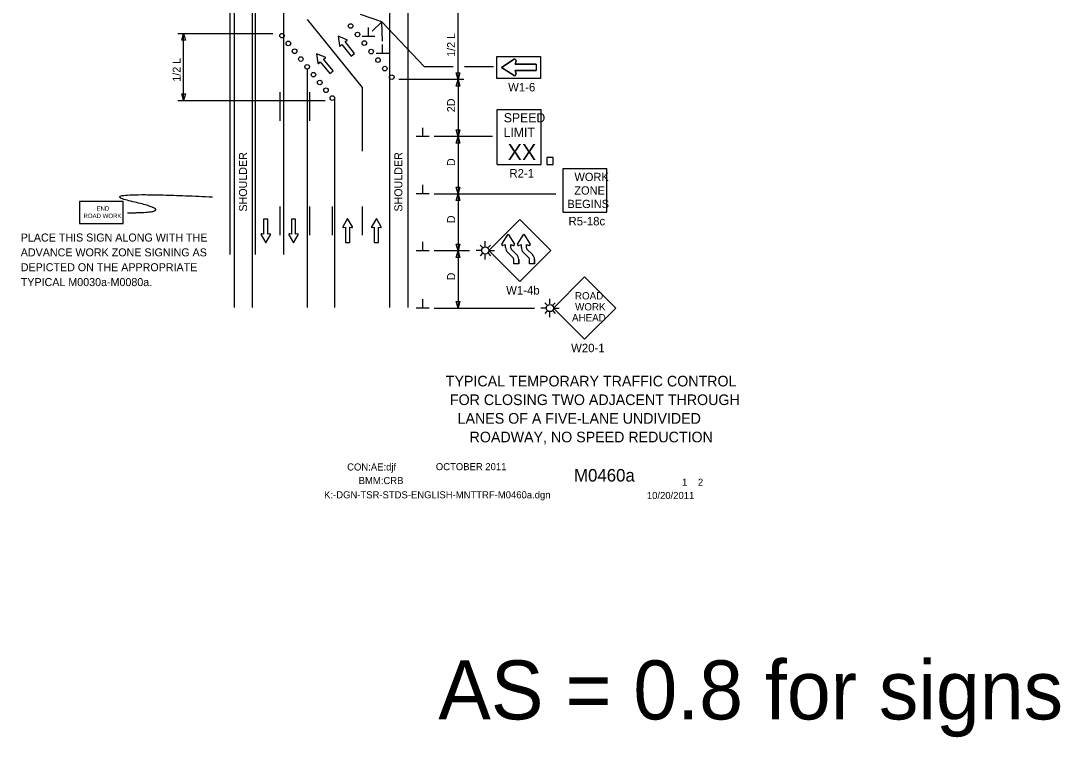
# Model space of a CAD drawing. Extents: x 16752 to 18475, y 7011 to 8262.
# Drawn here: x 16805 to 17715, y 7011 to 7638 of the extents above; entities that cross this region are included whole.
import ezdxf

# ---------------------------------------------------------------- set-up
doc = ezdxf.new("R2010")
doc.units = 0
for name, color, linetype in [('ALI_LEGAL_EX', 7, 'Continuous'), ('BORDER', 7, 'Continuous'), ('BORDER_SIGNAL_WO', 7, 'Continuous'), ('MT_SCRATCH_LEVEL_E', 7, 'Continuous'), ('PAVT_EDGE_EX', 7, 'Continuous'), ('TRAFFIC_SIGNS_PR', 7, 'Continuous'), ('TYPICAL_TEXT_DIMEN_PR', 7, 'Continuous')]:
    doc.layers.add(name, color=color, linetype=linetype)

msp = doc.modelspace()

# ---------------------------------------------------------------- linework, layer by layer
at = {"layer": 'ALI_LEGAL_EX'}
for points in [[(17031.71, 7575.16), (17031.71, 7550.16)], [(17057.71, 7575.16), (17057.71, 7550.16)], [(17103.71, 7571.6), (17103.71, 7550.16)], [(17031.71, 7475.16), (17031.71, 7450.16)], [(17057.71, 7475.16), (17057.71, 7450.16)], [(17077.71, 7475.16), (17077.71, 7450.16)], [(17103.71, 7475.16), (17103.71, 7450.16)]]:
    msp.add_lwpolyline(points, dxfattribs=at)
at = {"layer": 'BORDER'}
msp.add_line((17289.25, 7291.25), (17289.25, 7291.25), dxfattribs=at)
at = {"layer": 'MT_SCRATCH_LEVEL_E'}
for p, q in [((17082.7, 7624.22), (17084.04, 7616)), ((17090.47, 7621.18), (17082.7, 7624.22)), ((17082.7, 7624.22), (17084.04, 7616)), ((17090.47, 7621.18), (17082.7, 7624.22)), ((17084.84, 7615.77), (17086.03, 7617.13)), ((17084.84, 7615.77), (17086.03, 7617.13)), ((17086.03, 7617.13), (17094.34, 7606.81)), ((17086.03, 7617.13), (17094.34, 7606.81)), ((17088.94, 7619.48), (17090.52, 7620.35)), ((17088.94, 7619.48), (17090.52, 7620.35)), ((17097.26, 7609.15), (17088.94, 7619.48)), ((17097.26, 7609.15), (17088.94, 7619.48)), ((17063.77, 7608.9), (17065.11, 7600.68)), ((17071.54, 7605.86), (17063.77, 7608.9)), ((17063.77, 7608.9), (17065.11, 7600.68)), ((17071.54, 7605.86), (17063.77, 7608.9)), ((17070.01, 7604.16), (17071.6, 7605.03)), ((17070.01, 7604.16), (17071.6, 7605.03)), ((17078.33, 7593.83), (17070.01, 7604.16)), ((17078.33, 7593.83), (17070.01, 7604.16)), ((17094.34, 7606.81), (17097.26, 7609.15)), ((17094.34, 7606.81), (17097.26, 7609.15)), ((17065.91, 7600.45), (17067.1, 7601.81)), ((17065.91, 7600.45), (17067.1, 7601.81)), ((17067.1, 7601.81), (17075.42, 7591.49)), ((17067.1, 7601.81), (17075.42, 7591.49)), ((17075.42, 7591.49), (17078.33, 7593.83)), ((17075.42, 7591.49), (17078.33, 7593.83)), ((17021.38, 7464.24), (17017.64, 7464.24)), ((17017.64, 7464.24), (17017.64, 7450.98)), ((17021.38, 7464.24), (17017.64, 7464.24)), ((17017.64, 7464.24), (17017.64, 7450.98)), ((17021.38, 7450.98), (17021.38, 7464.24)), ((17021.38, 7450.98), (17021.38, 7464.24)), ((17045.64, 7464.24), (17041.9, 7464.24)), ((17041.9, 7464.24), (17041.9, 7450.98)), ((17045.64, 7464.24), (17041.9, 7464.24)), ((17041.9, 7464.24), (17041.9, 7450.98)), ((17045.64, 7450.98), (17045.64, 7464.24)), ((17045.64, 7450.98), (17045.64, 7464.24)), ((17091.15, 7464.69), (17087.04, 7457.45)), ((17091.15, 7464.69), (17087.04, 7457.45)), ((17095.3, 7457.45), (17091.15, 7464.69)), ((17095.3, 7457.45), (17091.15, 7464.69)), ((17116.24, 7464.69), (17112.13, 7457.45)), ((17116.24, 7464.69), (17112.13, 7457.45)), ((17120.39, 7457.45), (17116.24, 7464.69)), ((17120.39, 7457.45), (17116.24, 7464.69)), ((17015.38, 7450.61), (17019.53, 7443.37)), ((17015.38, 7450.61), (17019.53, 7443.37)), ((17017.64, 7450.98), (17015.86, 7451.29)), ((17017.64, 7450.98), (17015.86, 7451.29)), ((17019.53, 7443.37), (17023.64, 7450.61)), ((17019.53, 7443.37), (17023.64, 7450.61)), ((17023.16, 7451.29), (17021.38, 7450.98)), ((17023.16, 7451.29), (17021.38, 7450.98)), ((17039.64, 7450.61), (17043.79, 7443.37)), ((17039.64, 7450.61), (17043.79, 7443.37)), ((17041.9, 7450.98), (17040.12, 7451.29)), ((17041.9, 7450.98), (17040.12, 7451.29)), ((17043.79, 7443.37), (17047.9, 7450.61)), ((17043.79, 7443.37), (17047.9, 7450.61)), ((17047.42, 7451.29), (17045.64, 7450.98)), ((17047.42, 7451.29), (17045.64, 7450.98)), ((17087.52, 7456.77), (17089.3, 7457.09)), ((17087.52, 7456.77), (17089.3, 7457.09)), ((17089.3, 7457.09), (17089.3, 7443.83)), ((17089.3, 7457.09), (17089.3, 7443.83)), ((17093.04, 7443.83), (17093.04, 7457.09)), ((17093.04, 7457.09), (17094.82, 7456.77)), ((17093.04, 7443.83), (17093.04, 7457.09)), ((17093.04, 7457.09), (17094.82, 7456.77)), ((17112.61, 7456.77), (17114.39, 7457.09)), ((17112.61, 7456.77), (17114.39, 7457.09)), ((17114.39, 7457.09), (17114.39, 7443.83)), ((17114.39, 7457.09), (17114.39, 7443.83)), ((17118.13, 7443.83), (17118.13, 7457.09)), ((17118.13, 7457.09), (17119.91, 7456.77)), ((17118.13, 7443.83), (17118.13, 7457.09)), ((17118.13, 7457.09), (17119.91, 7456.77)), ((17089.3, 7443.83), (17093.04, 7443.83)), ((17089.3, 7443.83), (17093.04, 7443.83)), ((17114.39, 7443.83), (17118.13, 7443.83)), ((17114.39, 7443.83), (17118.13, 7443.83))]:
    msp.add_line(p, q, dxfattribs=at)
for centre, start, end in [((17090.29, 7620.75), 298.87699, 68.61391), ((17090.29, 7620.75), 298.87699, 68.61391), ((17084.49, 7616.08), 189.26563, 318.8046), ((17084.49, 7616.08), 189.26563, 318.8046), ((17071.36, 7605.43), 298.87699, 68.61391), ((17071.36, 7605.43), 298.87699, 68.61391), ((17065.57, 7600.76), 189.26563, 318.8046), ((17065.57, 7600.76), 189.26563, 318.8046), ((17087.45, 7457.23), 150.42484, 279.96381), ((17087.45, 7457.23), 150.42484, 279.96381), ((17094.89, 7457.23), 260.03619, 29.77312), ((17094.89, 7457.23), 260.03619, 29.77312), ((17112.54, 7457.23), 150.42484, 279.96381), ((17112.54, 7457.23), 150.42484, 279.96381), ((17119.98, 7457.23), 260.03619, 29.77312), ((17119.98, 7457.23), 260.03619, 29.77312), ((17015.79, 7450.83), 80.03619, 209.77312), ((17015.79, 7450.83), 80.03619, 209.77312), ((17023.23, 7450.83), 330.42484, 99.96381), ((17023.23, 7450.83), 330.42484, 99.96381), ((17040.05, 7450.83), 80.03619, 209.77312), ((17040.05, 7450.83), 80.03619, 209.77312), ((17047.49, 7450.83), 330.42484, 99.96381), ((17047.49, 7450.83), 330.42484, 99.96381)]:
    msp.add_arc(centre, 0.463, start, end, dxfattribs=at)
at = {"layer": 'PAVT_EDGE_EX'}
for p, q in [((16988.15, 8262.34), (16988.15, 7433.15)), ((17010.15, 8262.34), (17010.15, 7433.15)), ((17035.15, 8262.34), (17035.15, 7433.15)), ((16991.71, 8192.65), (16991.71, 7386.98)), ((17007.71, 8192.65), (17007.71, 7386.98)), ((17127.71, 8192.65), (17127.71, 7386.98)), ((17143.71, 8192.65), (17143.71, 7386.98)), ((17055.71, 7638.88), (17103.71, 7579.27)), ((17055.71, 7595.43), (17055.71, 7386.98)), ((17103.71, 7579.27), (17103.71, 7523.81)), ((17079.71, 7570.11), (17079.71, 7386.98))]:
    msp.add_line(p, q, dxfattribs=at)
at = {"layer": 'TRAFFIC_SIGNS_PR'}
for p, q in [((17236.76, 7604.04), (17225.6, 7596.94)), ((17237.6, 7599.74), (17238.44, 7602.8)), ((17225.6, 7596.94), (17236.76, 7589.83)), ((17256, 7599.74), (17237.6, 7599.74)), ((17238.44, 7591.08), (17237.6, 7594.14)), ((17237.6, 7594.14), (17256, 7594.14)), ((17256, 7599.74), (17256, 7594.14)), ((17221.98, 7560.05), (17260.38, 7560.05)), ((17221.98, 7512.05), (17221.98, 7560.05)), ((17260.38, 7512.05), (17260.38, 7560.05)), ((17221.98, 7512.05), (17260.38, 7512.05)), ((17279.56, 7470.17), (17279.56, 7508.57)), ((17279.56, 7508.57), (17317.96, 7508.57)), ((17317.96, 7470.17), (17317.96, 7508.57)), ((17279.56, 7470.17), (17317.96, 7470.17)), ((17214.72, 7436.83), (17241.87, 7463.98)), ((17241.87, 7463.98), (17269.03, 7436.83)), ((17209.05, 7439.34), (17206.94, 7441.45)), ((17211.57, 7440.38), (17211.57, 7444.89)), ((17214.08, 7439.34), (17216.19, 7441.45)), ((17208.41, 7436.83), (17203.57, 7436.83)), ((17209.05, 7434.32), (17206.94, 7432.21)), ((17211.57, 7428.86), (17211.57, 7433.28)), ((17214.08, 7434.32), (17216.19, 7432.21)), ((17214.72, 7436.83), (17219.6, 7436.83)), ((17241.87, 7409.68), (17214.72, 7436.83)), ((17235.89, 7430.31), (17231.18, 7435.03)), ((17235.89, 7430.31), (17231.18, 7435.03)), ((17238.94, 7433.36), (17234.23, 7438.08)), ((17234.23, 7438.08), (17238.94, 7433.36)), ((17269.03, 7436.83), (17241.87, 7409.68)), ((17249.69, 7430.31), (17244.97, 7435.03)), ((17249.69, 7430.31), (17244.97, 7435.03)), ((17252.74, 7433.36), (17248.03, 7438.08)), ((17248.03, 7438.08), (17252.74, 7433.36)), ((17236.49, 7425.24), (17236.49, 7428.94)), ((17240.81, 7425.24), (17236.49, 7425.24)), ((17240.81, 7425.24), (17240.81, 7428.94)), ((17250.29, 7425.24), (17250.29, 7428.94)), ((17254.61, 7425.24), (17250.29, 7425.24)), ((17254.61, 7425.24), (17254.61, 7428.94)), ((17298.49, 7413.61), (17271.3, 7386.42)), ((17325.68, 7386.42), (17298.49, 7413.61)), ((17268.15, 7389.98), (17268.15, 7394.48)), ((17264.99, 7386.42), (17260.16, 7386.42)), ((17265.64, 7388.93), (17263.53, 7391.04)), ((17270.66, 7388.93), (17272.77, 7391.04)), ((17271.3, 7386.42), (17276.18, 7386.42)), ((17271.3, 7386.42), (17298.49, 7359.23)), ((17298.49, 7359.23), (17325.68, 7386.42)), ((17265.63, 7383.91), (17263.53, 7381.8)), ((17268.15, 7378.45), (17268.15, 7382.87)), ((17270.66, 7383.91), (17272.77, 7381.8))]:
    msp.add_line(p, q, dxfattribs=at)
for points in [[(17260, 7587.34), (17221.6, 7587.34), (17221.6, 7606.54), (17260, 7606.54)], [(17265.4, 7512.05), (17270.99, 7512.05), (17270.99, 7518.22), (17265.4, 7518.22)], [(16856.43, 7460.42), (16894.83, 7460.42), (16894.83, 7479.62), (16856.43, 7479.62)]]:
    msp.add_lwpolyline(points, close=True, dxfattribs=at)
for points in [[(17236.76, 7589.83), (17225.6, 7596.94), (17236.76, 7604.04)], [(17238.44, 7602.8), (17237.6, 7599.74), (17256, 7599.74), (17256, 7594.14), (17237.6, 7594.14), (17238.44, 7591.08)], [(17226.02, 7442.35), (17231.51, 7450.96), (17236.99, 7442.35)], [(17226.02, 7442.35), (17231.51, 7450.96), (17236.99, 7442.35)], [(17239.82, 7442.35), (17245.3, 7450.96), (17250.78, 7442.35)], [(17239.82, 7442.35), (17245.3, 7450.96), (17250.78, 7442.35)], [(17229.35, 7439.34), (17229.35, 7441.7), (17226.98, 7441.06)], [(17229.35, 7439.34), (17229.35, 7441.7), (17226.98, 7441.06)], [(17236.03, 7441.05), (17233.67, 7441.7), (17233.67, 7439.41)], [(17236.03, 7441.05), (17235.19, 7441.28), (17233.67, 7441.7), (17233.67, 7439.41)], [(17243.15, 7439.34), (17243.15, 7441.7), (17240.78, 7441.06)], [(17243.15, 7439.34), (17243.15, 7441.7), (17240.78, 7441.06)], [(17249.82, 7441.05), (17247.46, 7441.7), (17247.47, 7439.41)], [(17249.82, 7441.05), (17248.99, 7441.28), (17247.46, 7441.7), (17247.47, 7439.41)], [(17240.81, 7428.94), (17240.81, 7425.24), (17236.49, 7425.24), (17236.49, 7428.94)], [(17254.61, 7428.94), (17254.61, 7425.24), (17250.29, 7425.24), (17250.29, 7428.94)]]:
    msp.add_lwpolyline(points, dxfattribs=at)
for centre, radius in [((17093.71, 7633.15), 2), ((17033.71, 7624.75), 2), ((17099.71, 7625.7), 2), ((17039.21, 7617.92), 2), ((17044.71, 7611.09), 2), ((17105.71, 7618.25), 2), ((17111.71, 7610.8), 2), ((17050.21, 7604.26), 2), ((17117.71, 7603.34), 2), ((17055.71, 7597.43), 2), ((17123.71, 7595.89), 2), ((17061.21, 7590.6), 2), ((17066.71, 7583.77), 2), ((17129.71, 7588.44), 2), ((17072.21, 7576.94), 2), ((17077.71, 7570.11), 2), ((17211.57, 7436.83), 3.15), ((17268.15, 7386.42), 3.15)]:
    msp.add_circle(centre, radius, dxfattribs=at)
for centre, radius, start, end in [((17237.36, 7603.09), 1.12, 344.67308, 122.46963), ((17237.36, 7603.09), 1.12, 344.67308, 122.46962), ((17237.36, 7590.78), 1.12, 237.53038, 15.32692), ((17237.36, 7590.78), 1.12, 237.53038, 15.32692), ((17226.76, 7441.89), 0.866, 147.7292, 285.31719), ((17226.76, 7441.89), 0.866, 147.71964, 285.32011), ((17216.91, 7448.15), 10.8, 327.53351, 327.54311), ((17229.84, 7430.64), 10.8, 105.31922, 105.32004), ((17235.52, 7439.4), 6.17, 180.61811, 225.78746), ((17235.52, 7439.4), 6.17, 180.62445, 225.23128), ((17235.52, 7439.4), 1.85, 179.8762, 225.7877), ((17235.52, 7439.4), 1.85, 180, 225.78746), ((17236.26, 7441.89), 0.864, 254.6014, 32.47956), ((17236.26, 7441.89), 0.866, 254.61481, 32.47119), ((17240.55, 7441.89), 0.866, 147.7292, 285.31719), ((17240.55, 7441.89), 0.866, 147.71964, 285.32011), ((17230.71, 7448.15), 10.8, 327.53351, 327.54311), ((17243.63, 7430.64), 10.8, 105.31922, 105.32004), ((17249.32, 7439.4), 6.17, 180.61811, 225.78746), ((17249.32, 7439.4), 6.17, 180.62445, 225.23128), ((17249.32, 7439.4), 1.85, 179.8762, 225.7877), ((17249.32, 7439.4), 1.85, 180, 225.78746), ((17250.05, 7441.89), 0.864, 254.6014, 32.47956), ((17250.05, 7441.89), 0.866, 254.61481, 32.47119), ((17234.64, 7428.94), 1.85, 0, 47.62801), ((17234.64, 7428.94), 1.85, 0, 45.78746), ((17234.64, 7428.94), 6.17, 0, 45.78746), ((17234.64, 7428.94), 6.17, 0, 45.78746), ((17234.64, 7428.94), 6.17, 0, 45.78828), ((17248.44, 7428.94), 1.85, 0, 47.62801), ((17248.44, 7428.94), 1.85, 0, 45.78746), ((17248.44, 7428.94), 6.17, 0, 45.78746), ((17248.44, 7428.94), 6.17, 0, 45.78746), ((17248.44, 7428.94), 6.17, 0, 45.78828)]:
    msp.add_arc(centre, radius, start, end, dxfattribs=at)
msp.add_open_spline([(16898.42, 7469.8), (16945.66, 7469.8), (16860.63, 7489.14), (16972.93, 7483.65)], degree=2, dxfattribs=at)
at = {"layer": 'TYPICAL_TEXT_DIMEN_PR'}
for p, q in [((17187.71, 7586.44), (17187.71, 7650.11)), ((17187.71, 7586.44), (17187.71, 7650.11)), ((17121.1, 7636.86), (17102.26, 7643.12)), ((17109.37, 7624.12), (17109.37, 7631.91)), ((17121.1, 7636.86), (17112.51, 7628.66)), ((17121.66, 7620.04), (17121.1, 7636.86)), ((17121.1, 7636.86), (17158.2, 7597.83)), ((16942.61, 7626.75), (17025.7, 7626.75)), ((16946.04, 7620.89), (16947.61, 7626.75)), ((16947.61, 7620.89), (16946.04, 7620.89)), ((16947.61, 7626.75), (16949.18, 7620.89)), ((16947.61, 7568.1), (16947.61, 7626.75)), ((16949.18, 7620.89), (16947.61, 7620.89)), ((17114.99, 7624.12), (17103.74, 7624.12)), ((17121.59, 7609.26), (17121.59, 7617.05)), ((17127.22, 7609.26), (17115.97, 7609.26)), ((17158.2, 7597.83), (17183.44, 7597.83)), ((17193.36, 7597.83), (17218.89, 7597.83)), ((17192.71, 7586.44), (17136.05, 7586.44)), ((17187.71, 7586.44), (17186.14, 7592.3)), ((17186.14, 7592.3), (17187.71, 7592.3)), ((17187.71, 7586.44), (17186.14, 7592.3)), ((17186.14, 7592.3), (17187.71, 7592.3)), ((17186.14, 7580.58), (17187.71, 7586.44)), ((17187.71, 7592.3), (17189.28, 7592.3)), ((17189.28, 7592.3), (17187.71, 7586.44)), ((17187.71, 7592.3), (17189.28, 7592.3)), ((17189.28, 7592.3), (17187.71, 7586.44)), ((17187.71, 7586.44), (17187.71, 7536.44)), ((17187.71, 7586.44), (17189.28, 7580.58)), ((17187.71, 7580.58), (17186.14, 7580.58)), ((17189.28, 7580.58), (17187.71, 7580.58)), ((16942.61, 7568.11), (17071.46, 7568.11)), ((16947.61, 7568.1), (16946.04, 7573.97)), ((16946.04, 7573.97), (16947.61, 7573.97)), ((16947.61, 7573.97), (16949.18, 7573.97)), ((16949.18, 7573.97), (16947.61, 7568.1)), ((17156.84, 7536.44), (17156.84, 7544.23)), ((17187.71, 7536.44), (17186.14, 7542.3)), ((17186.14, 7542.3), (17187.71, 7542.3)), ((17187.71, 7542.3), (17189.28, 7542.3)), ((17189.28, 7542.3), (17187.71, 7536.44)), ((17162.46, 7536.44), (17151.21, 7536.44)), ((17217.88, 7536.44), (17166.71, 7536.44)), ((17186.14, 7530.58), (17187.71, 7536.44)), ((17187.71, 7530.58), (17186.14, 7530.58)), ((17187.71, 7536.44), (17189.28, 7530.58)), ((17187.71, 7536.44), (17187.71, 7486.44)), ((17189.28, 7530.58), (17187.71, 7530.58)), ((17156.84, 7486.44), (17156.84, 7494.23)), ((17162.46, 7486.44), (17151.21, 7486.44)), ((17166.71, 7486.44), (17273.4, 7486.44)), ((17187.71, 7486.44), (17186.14, 7492.3)), ((17186.14, 7492.3), (17187.71, 7492.3)), ((17186.14, 7480.58), (17187.71, 7486.44)), ((17187.71, 7492.3), (17189.28, 7492.3)), ((17189.28, 7492.3), (17187.71, 7486.44)), ((17187.71, 7486.44), (17187.71, 7436.44)), ((17187.71, 7486.44), (17189.28, 7480.58)), ((17187.71, 7480.58), (17186.14, 7480.58)), ((17189.28, 7480.58), (17187.71, 7480.58)), ((17156.84, 7436.44), (17156.84, 7444.23)), ((17187.71, 7436.44), (17186.14, 7442.3)), ((17186.14, 7442.3), (17187.71, 7442.3)), ((17187.71, 7442.3), (17189.28, 7442.3)), ((17189.28, 7442.3), (17187.71, 7436.44)), ((17162.46, 7436.44), (17151.21, 7436.44)), ((17197.83, 7436.44), (17166.71, 7436.44)), ((17186.14, 7430.58), (17187.71, 7436.44)), ((17187.71, 7430.58), (17186.14, 7430.58)), ((17187.71, 7436.44), (17189.28, 7430.58)), ((17187.71, 7436.44), (17187.71, 7386.44)), ((17189.28, 7430.58), (17187.71, 7430.58)), ((17156.84, 7386.44), (17156.84, 7394.23)), ((17162.46, 7386.44), (17151.21, 7386.44)), ((17166.71, 7386.44), (17254.64, 7386.44)), ((17187.71, 7386.44), (17186.14, 7392.3)), ((17186.14, 7392.3), (17187.71, 7392.3)), ((17187.71, 7392.3), (17189.28, 7392.3)), ((17189.28, 7392.3), (17187.71, 7386.44))]:
    msp.add_line(p, q, dxfattribs=at)

# ---------------------------------------------------------------- texts
at = {"layer": 'BORDER'}
for s, p in [('TYPICAL TEMPORARY TRAFFIC CONTROL', (17177.02, 7317.87)), ('FOR CLOSING TWO ADJACENT THROUGH', (17180.6, 7301.57)), ('LANES OF A FIVE-LANE UNDIVIDED', (17187.36, 7285.27)), ('ROADWAY, NO SPEED REDUCTION', (17197.83, 7268.97))]:
    msp.add_text(s, height=9.3, dxfattribs=at).set_placement(p)
at = {"layer": 'BORDER_SIGNAL_WO'}
for s, height, p in [('CON:AE:djf', 6.2, (17090.69, 7244.31)), ('    OCTOBER 2011    ', 6.2, (17159.08, 7244.59)), ('    M0460a   ', 11, (17272.86, 7234.63)), ('BMM:CRB   ', 6.2, (17100.81, 7232.42)), (' 1    2 ', 6.2, (17381.45, 7230.95)), ('K:-DGN-TSR-STDS-ENGLISH-MNTTRF-M0460a.dgn        ', 6.2, (17070.55, 7219.96)), ('10/20/2011    ', 6.2, (17352.93, 7219.38)), ('AS = 0.8 for signs', 51.6096, (17170.41, 7026.56))]:
    msp.add_text(s, height=height, dxfattribs=at).set_placement(p)
at = {"layer": 'TRAFFIC_SIGNS_PR'}
for s, height, p in [('W1-6', 7.44, (17231.54, 7575.9)), ('SPEED', 8, (17227.75, 7548.91)), ('LIMIT', 8, (17227.59, 7536.11)), ('XX', 14.031, (17231.1, 7515.81)), ('R2-1', 7.44, (17232.66, 7500.61)), ('WORK', 7.217, (17289.56, 7497.53)), ('ZONE', 7.217, (17289.44, 7485.72)), ('END', 3.831, (16871.43, 7471.55)), ('BEGINS', 7.217, (17283.37, 7473.91)), ('ROAD WORK', 3.831, (16860.04, 7465.16)), ('R5-18c', 7.44, (17284.37, 7458.73)), ('PLACE THIS SIGN ALONG WITH THE', 7, (16805.15, 7444.64)), ('ADVANCE WORK ZONE SIGNING AS', 7, (16805.15, 7431.64)), ('DEPICTED ON THE APPROPRIATE', 7, (16805.15, 7418.64)), ('TYPICAL M0030a-M0080a.', 7, (16805.15, 7405.64)), ('W1-4b', 7.44, (17229.83, 7398.24)), ('ROAD', 6.408, (17290.02, 7393.96)), ('WORK', 6.408, (17290.13, 7384.35)), ('AHEAD', 6.408, (17287.43, 7374.74)), ('W20-1', 7.449, (17286.64, 7347.78))]:
    msp.add_text(s, height=height, dxfattribs=at).set_placement(p)
at = {"layer": 'TYPICAL_TEXT_DIMEN_PR'}
for s, p in [('1/2 L', (17185.15, 7606.21)), ('1/2 L', (17185.15, 7606.21)), ('1/2 L', (16945.06, 7584.47)), ('2D', (17185.15, 7557.78)), ('SHOULDER', (17003.09, 7470.8)), ('SHOULDER', (17138.99, 7470.8)), ('D', (17185.15, 7510.66)), ('D', (17185.15, 7460.66)), ('D', (17185.15, 7410.66))]:
    msp.add_text(s, height=7, rotation=90, dxfattribs=at).set_placement(p)

doc.saveas('drawing.dxf')
